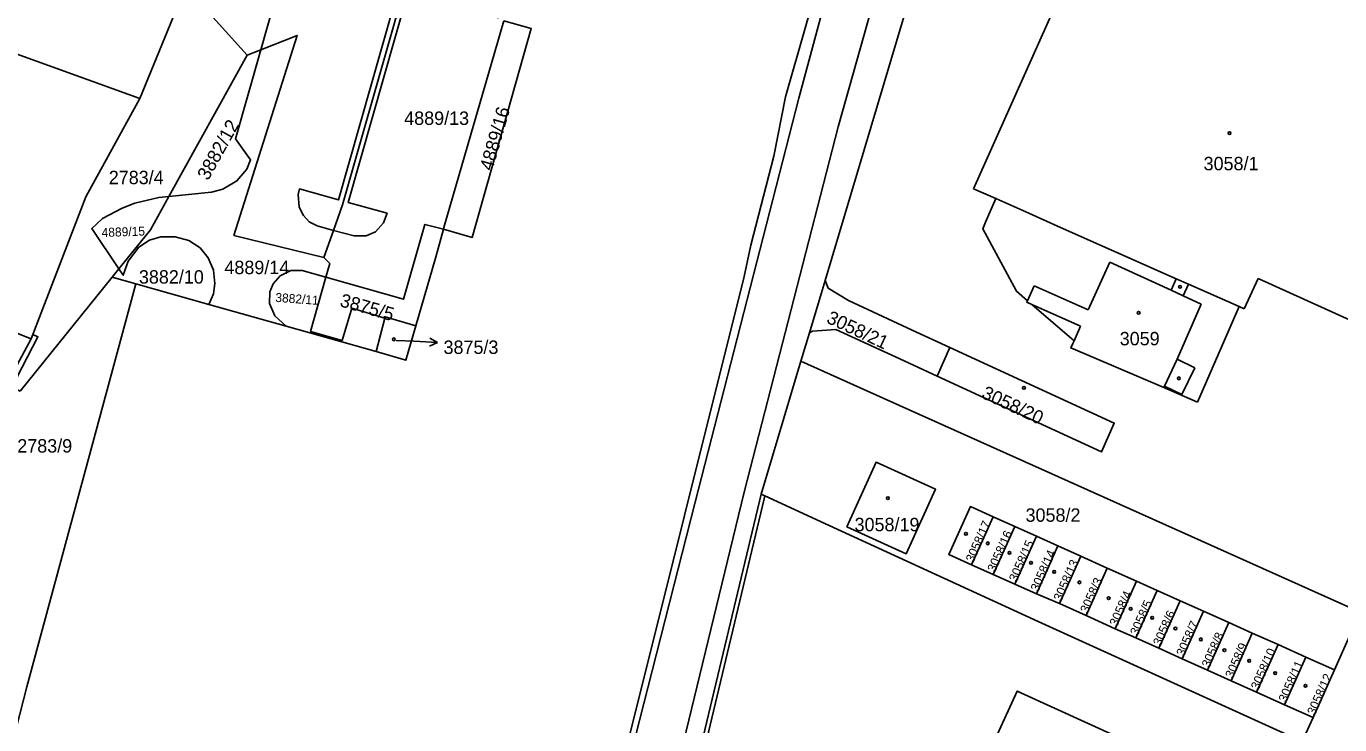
# Model space of a CAD drawing. Extents: x -527335 to -526256, y -1079142 to -1077809.
# Drawn here: x -526891.4 to -526725, y -1078894.6 to -1078806.1 of the extents above; entities that cross this region are included whole.
import ezdxf

# ---------------------------------------------------------------- set-up
doc = ezdxf.new("R2010")
doc.units = 0
for name, color, linetype in [('Vrstva 1', 7, 'Continuous'), ('Vrstva 2', 7, 'Continuous'), ('Vrstva 4', 7, 'Continuous'), ('Vrstva 5', 7, 'Continuous'), ('Vrstva 7', 7, 'Continuous')]:
    doc.layers.add(name, color=color, linetype=linetype)

msp = doc.modelspace()

# ---------------------------------------------------------------- linework, layer by layer
at = {"layer": 'Vrstva 1'}
for p, q in [((-526774.18, -1078784.68), (-526790.21, -1078838.32)), ((-526871.22, -1078801.11), (-526877.03, -1078815.27)), ((-526863.41, -1078809.75), (-526871.22, -1078801.11)), ((-526877.03, -1078815.27), (-526901.79, -1078806.32)), ((-526863.41, -1078809.75), (-526861.71, -1078809.08)), ((-526873.33, -1078827.67), (-526863.41, -1078809.75)), ((-526853.71, -1078835.4), (-526852.48, -1078831.96)), ((-526880.51, -1078837.89), (-526879.67, -1078836.85)), ((-526880.51, -1078837.89), (-526892.2, -1078852.35)), ((-526790.21, -1078838.32), (-526792.2, -1078844.96)), ((-526858.47, -1078844.1), (-526868.27, -1078841.34)), ((-526896.06, -1078843.62), (-526890.8, -1078845.7)), ((-526847.07, -1078847.31), (-526858.47, -1078844.1)), ((-526845.98, -1078843.08), (-526847.07, -1078847.31)), ((-526890.8, -1078845.7), (-526890.59, -1078845.16)), ((-526792.2, -1078844.96), (-526793.27, -1078848.55)), ((-526774.41, -1078846.79), (-526776, -1078850.44)), ((-526793.27, -1078848.55), (-526798.3, -1078865.38)), ((-526768.92, -1078868.26), (-526771.65, -1078874.34)), ((-526768.92, -1078868.26), (-526766.18, -1078869.49)), ((-526766.18, -1078869.49), (-526768.91, -1078875.57)), ((-526766.18, -1078869.49), (-526763.44, -1078870.72)), ((-526763.44, -1078870.72), (-526766.17, -1078876.8)), ((-526763.44, -1078870.72), (-526760.7, -1078871.95)), ((-526760.7, -1078871.95), (-526763.43, -1078878.03)), ((-526760.7, -1078871.95), (-526757.82, -1078873.24)), ((-526768.91, -1078875.57), (-526771.65, -1078874.34)), ((-526757.82, -1078873.24), (-526760.52, -1078879.26)), ((-526757.82, -1078873.24), (-526754.45, -1078874.76)), ((-526766.17, -1078876.8), (-526768.91, -1078875.57)), ((-526757.15, -1078880.77), (-526754.45, -1078874.76)), ((-526754.45, -1078874.76), (-526750.74, -1078876.42)), ((-526763.43, -1078878.03), (-526766.17, -1078876.8)), ((-526753.44, -1078882.44), (-526750.74, -1078876.42)), ((-526750.83, -1078883.61), (-526748.13, -1078877.59)), ((-526750.74, -1078876.42), (-526748.13, -1078877.59)), ((-526748.13, -1078877.59), (-526745.22, -1078878.9)), ((-526760.52, -1078879.26), (-526763.43, -1078878.03)), ((-526757.15, -1078880.77), (-526760.52, -1078879.26)), ((-526747.92, -1078884.92), (-526745.22, -1078878.9)), ((-526745.22, -1078878.9), (-526742.26, -1078880.23)), ((-526753.44, -1078882.44), (-526757.15, -1078880.77)), ((-526744.97, -1078886.25), (-526742.26, -1078880.23)), ((-526742.26, -1078880.23), (-526739.06, -1078881.66)), ((-526750.83, -1078883.61), (-526753.44, -1078882.44)), ((-526741.76, -1078887.69), (-526739.06, -1078881.66)), ((-526739.06, -1078881.66), (-526736.08, -1078883)), ((-526747.92, -1078884.92), (-526750.83, -1078883.61)), ((-526738.78, -1078889.03), (-526736.08, -1078883)), ((-526736.08, -1078883), (-526732.82, -1078884.46)), ((-526744.97, -1078886.25), (-526747.92, -1078884.92)), ((-526735.53, -1078890.49), (-526732.82, -1078884.46)), ((-526732.82, -1078884.46), (-526729.32, -1078886.04)), ((-526732.02, -1078892.07), (-526729.32, -1078886.04)), ((-526729.32, -1078886.04), (-526725.68, -1078887.67)), ((-526741.76, -1078887.69), (-526744.97, -1078886.25)), ((-526738.78, -1078889.03), (-526741.76, -1078887.69)), ((-526725.68, -1078887.67), (-526728.39, -1078893.7)), ((-526735.53, -1078890.49), (-526738.78, -1078889.03)), ((-526732.02, -1078892.07), (-526735.53, -1078890.49)), ((-526728.39, -1078893.7), (-526732.02, -1078892.07)), ((-526728.39, -1078893.7), (-526729.75, -1078896.73))]:
    msp.add_line(p, q, dxfattribs=at)
for points in [[(-526884.44, -1079141.53), (-526861.26, -1079084.28), (-526853.99, -1079074.79), (-526822.82, -1079003.24), (-526818.77, -1078991.73), (-526809.1, -1078957.32), (-526811.39, -1078950.51), (-526823.11, -1078928.49), (-526800.47, -1078837.81), (-526799.62, -1078833.84), (-526796.71, -1078822.54), (-526795.22, -1078815.04), (-526782.49, -1078770.61), (-526773.56, -1078736.49), (-526766.02, -1078728.13)], [(-526852.48, -1078831.96), (-526854.54, -1078831.4), (-526855.56, -1078830.87), (-526856.3, -1078830.07), (-526856.84, -1078829.04), (-526856.96, -1078827.42), (-526856.79, -1078826.7), (-526851.86, -1078828.1), (-526840.8, -1078789.17), (-526845.77, -1078787.84), (-526843.88, -1078781.19), (-526838.92, -1078782.52), (-526834.15, -1078765.67), (-526839.09, -1078764.32), (-526834.71, -1078748.94), (-526829.81, -1078750.39), (-526823.64, -1078728.74)], [(-526853.42, -1078763.04), (-526851.9, -1078763.85), (-526850.58, -1078764.43), (-526849.29, -1078765.38), (-526848.37, -1078766.67), (-526847.89, -1078768.42), (-526848.14, -1078770.69), (-526851.19, -1078772.01), (-526854.35, -1078783.07), (-526852.4, -1078785.74), (-526853.18, -1078788.48), (-526856.25, -1078789.82), (-526861.71, -1078809.08)], [(-526838.29, -1078782.98), (-526851.34, -1078828.74), (-526852.48, -1078831.96)], [(-526852.48, -1078831.96), (-526849.88, -1078832.66), (-526848.34, -1078832.64), (-526847.17, -1078832.15), (-526846.16, -1078831.02), (-526845.7, -1078829.8), (-526850.63, -1078828.45), (-526843.06, -1078801.82), (-526831.53, -1078805.04)], [(-526830.92, -1078805.41), (-526827.43, -1078806.4), (-526834.91, -1078832.86), (-526838.57, -1078831.82)], [(-526838.57, -1078831.82), (-526838.51, -1078831.59), (-526830.92, -1078805.41)], [(-526861.71, -1078809.08), (-526857.09, -1078807.27), (-526865.1, -1078832.61), (-526853.71, -1078835.4)], [(-526861.71, -1078809.08), (-526864.9, -1078820.36), (-526862.99, -1078823.04), (-526863.47, -1078824.2), (-526864.73, -1078825.69), (-526866.5, -1078826.75), (-526867.93, -1078827.11), (-526873.33, -1078827.67)], [(-526890.59, -1078845.16), (-526883.88, -1078827.7), (-526877.03, -1078815.27)], [(-526879.67, -1078836.85), (-526883.11, -1078831.73), (-526881.77, -1078830.48), (-526879.27, -1078829.14), (-526877.67, -1078828.53), (-526874.63, -1078827.81), (-526873.33, -1078827.67)], [(-526873.33, -1078827.67), (-526875.66, -1078831.89), (-526879.67, -1078836.85)], [(-526743.04, -1078853.75), (-526747.3, -1078851.87), (-526759.08, -1078846.86), (-526758.82, -1078846.29), (-526758.67, -1078845.95), (-526764.01, -1078841.37), (-526764.65, -1078841.08), (-526764.56, -1078840.89), (-526765.97, -1078839.68), (-526770.24, -1078831.76), (-526769.88, -1078830.92), (-526768.59, -1078827.94), (-526764.41, -1078829.8), (-526760.75, -1078831.42), (-526745.71, -1078838.09), (-526744.16, -1078838.78), (-526737.76, -1078841.62), (-526743.04, -1078853.75)], [(-526868.27, -1078841.34), (-526867.71, -1078840.01), (-526867.51, -1078838.71), (-526867.69, -1078837.02), (-526868.37, -1078835.46), (-526869.4, -1078834.19), (-526870.82, -1078833.24), (-526872.55, -1078832.77), (-526874.35, -1078832.78), (-526875.82, -1078833.22), (-526877.17, -1078834.08), (-526878.52, -1078835.85), (-526879.13, -1078837.66), (-526879.67, -1078836.85)], [(-526853.45, -1078837.91), (-526843.6, -1078840.7), (-526840.9, -1078831.21), (-526838.57, -1078831.82)], [(-526838.57, -1078831.82), (-526839.55, -1078835.47), (-526842.04, -1078844.04)], [(-526853.71, -1078835.4), (-526852.96, -1078836.18), (-526853.45, -1078837.91)], [(-526858.47, -1078844.1), (-526859.93, -1078842.78), (-526860.61, -1078841.23), (-526860.55, -1078839.74), (-526860.13, -1078838.75), (-526859.23, -1078837.72), (-526857.88, -1078837.05), (-526856.47, -1078837.05), (-526853.45, -1078837.91)], [(-526868.27, -1078841.34), (-526877.52, -1078838.73), (-526880.51, -1078837.89)], [(-526853.45, -1078837.91), (-526855.39, -1078844.76), (-526851.4, -1078845.9), (-526850.15, -1078841.82), (-526845.98, -1078843.08)], [(-526790.21, -1078838.32), (-526789.81, -1078839.3), (-526787.25, -1078840.87), (-526779.18, -1078844.59), (-526774.41, -1078846.79)], [(-526842.04, -1078844.04), (-526843.31, -1078848.43), (-526847.07, -1078847.31)], [(-526842.04, -1078844.04), (-526845.93, -1078842.9), (-526845.98, -1078843.08)], [(-526898.78, -1078860.48), (-526897.08, -1078857.34), (-526890.8, -1078845.7)], [(-526892.2, -1078852.35), (-526893.23, -1078851.84), (-526889.93, -1078845.45), (-526890.59, -1078845.16)], [(-526776, -1078850.44), (-526780.74, -1078848.26), (-526788.84, -1078844.53), (-526791.8, -1078844.72), (-526792.2, -1078844.96)], [(-526774.41, -1078846.79), (-526753.58, -1078856.38), (-526755.17, -1078860.03), (-526776, -1078850.44)], [(-526793.27, -1078848.55), (-526782.84, -1078853.23), (-526722.4, -1078880.36), (-526725.68, -1078887.67)], [(-526787.47, -1078869.51), (-526783.74, -1078861.33), (-526776.2, -1078864.77), (-526779.93, -1078872.94), (-526787.47, -1078869.51)], [(-526798.3, -1078865.38), (-526811.61, -1078921.08), (-526810.31, -1078930.61), (-526807.74, -1078936.51), (-526806.27, -1078939.34), (-526804.43, -1078942.06), (-526791.96, -1078947.57)], [(-526798.3, -1078865.38), (-526797.84, -1078865.59), (-526789.67, -1078869.35), (-526763.21, -1078881.51), (-526729.75, -1078896.73)], [(-526771.65, -1078874.34), (-526774.53, -1078873.05), (-526771.8, -1078866.97), (-526768.92, -1078868.26)], [(-526771.85, -1078903.46), (-526765.87, -1078890.34), (-526739.82, -1078902.21)]]:
    msp.add_lwpolyline(points, dxfattribs=at)
at = {"layer": 'Vrstva 4'}
for p, q in [((-526784.46, -1078781.51), (-526793.55, -1078815.2)), ((-526778.89, -1078784.53), (-526788.56, -1078818.84)), ((-526771.41, -1078826.69), (-526760.66, -1078802.66)), ((-526793.55, -1078815.2), (-526806.66, -1078866.4)), ((-526788.56, -1078818.84), (-526800.46, -1078865.14)), ((-526768.59, -1078827.94), (-526771.41, -1078826.69)), ((-526756.89, -1078842.04), (-526754.14, -1078835.98)), ((-526754.14, -1078835.98), (-526746.37, -1078839.55)), ((-526877.52, -1078838.73), (-526891.36, -1078889.81)), ((-526764.56, -1078840.89), (-526763.7, -1078839)), ((-526763.7, -1078839), (-526756.89, -1078842.04)), ((-526746.37, -1078839.55), (-526745.71, -1078838.09)), ((-526744.16, -1078838.78), (-526744.83, -1078840.26)), ((-526737.13, -1078841.9), (-526735.32, -1078838.08)), ((-526735.32, -1078838.08), (-526723.31, -1078843.53)), ((-526744.83, -1078840.26), (-526746.37, -1078839.55)), ((-526744.83, -1078840.26), (-526742.56, -1078841.3)), ((-526757.83, -1078844.12), (-526764.01, -1078841.37)), ((-526742.56, -1078841.3), (-526745.59, -1078848.3)), ((-526737.76, -1078841.62), (-526737.13, -1078841.9)), ((-526758.67, -1078845.95), (-526757.83, -1078844.12)), ((-526747.22, -1078851.7), (-526745.59, -1078848.3)), ((-526745.59, -1078848.3), (-526743.36, -1078849.37)), ((-526743.36, -1078849.37), (-526745, -1078852.77)), ((-526747.22, -1078851.7), (-526747.3, -1078851.87)), ((-526745, -1078852.77), (-526747.22, -1078851.7)), ((-526800.46, -1078865.14), (-526812.19, -1078913.33)), ((-526811.13, -1078921.2), (-526797.93, -1078865.98)), ((-526797.93, -1078865.98), (-526797.84, -1078865.59)), ((-526806.66, -1078866.4), (-526818.03, -1078910.91)), ((-526891.36, -1078889.81), (-526913.97, -1078978.24))]:
    msp.add_line(p, q, dxfattribs=at)
at = {"layer": 'Vrstva 5'}
for centre in [(-526738.96, -1078819.64), (-526745.24, -1078839.13), (-526750.48, -1078842.41), (-526844.83, -1078845.77), (-526745.38, -1078850.71), (-526765.01, -1078851.93), (-526782.25, -1078865.9), (-526772.36, -1078870.42), (-526769.6, -1078871.62), (-526766.85, -1078872.81), (-526764.12, -1078874.08), (-526761.18, -1078875.24), (-526757.99, -1078876.56), (-526754.28, -1078878.57), (-526751.49, -1078879.91), (-526748.76, -1078881.05), (-526745.83, -1078882.41), (-526742.59, -1078883.79), (-526739.62, -1078885.16), (-526736.47, -1078886.5), (-526733.18, -1078888.06), (-526729.35, -1078889.67)]:
    msp.add_circle(centre, 0.175, dxfattribs=at)
at = {"layer": 'Vrstva 7'}
for p, q in [((-526844.55, -1078845.91), (-526842.3, -1078846.02)), ((-526842.3, -1078846.02), (-526839.3, -1078846.18)), ((-526839.3, -1078846.18), (-526840.28, -1078845.62)), ((-526839.3, -1078846.18), (-526840.33, -1078846.62))]:
    msp.add_line(p, q, dxfattribs=at)

# ---------------------------------------------------------------- texts
at = {"layer": 'Vrstva 2'}
for s, p in [('4889/13', (-526843.53, -1078818.6)), ('3058/1', (-526742.25, -1078824.35)), ('2783/4', (-526880.96, -1078826.11)), ('4889/14', (-526866.31, -1078837.51)), ('3882/10', (-526877.14, -1078838.71)), ('3875/3', (-526838.55, -1078847.62)), ('3059', (-526752.88, -1078846.53)), ('2783/9', (-526892.55, -1078860.12)), ('3058/2', (-526764.81, -1078868.89)), ('3058/19', (-526786.47, -1078870.09))]:
    msp.add_text(s, height=1.7, dxfattribs=at).set_placement(p)
for s, height, rotation, p in [('4889/16', 1.7, 74, (-526832.37, -1078824.5)), ('3882/12', 1.7, 61, (-526868.37, -1078825.74)), ('4889/15', 1.139, 2, (-526881.85, -1078832.81)), ('3882/11', 1.139, 356, (-526859.89, -1078841.02)), ('3875/5', 1.7, 344, (-526851.79, -1078841.56)), ('3058/21', 1.7, 335, (-526790.15, -1078843.61)), ('3058/20', 1.7, 335, (-526770.5, -1078853.14)), ('3058/17', 1.14, 66, (-526771.41, -1078874.13)), ('3058/16', 1.14, 66, (-526768.67, -1078875.36)), ('3058/15', 1.14, 66, (-526765.93, -1078876.59)), ('3058/14', 1.14, 66, (-526763.19, -1078877.82)), ('3058/13', 1.14, 66, (-526760.28, -1078879.05)), ('3058/3', 1.14, 66, (-526756.91, -1078880.56)), ('3058/4', 1.14, 66, (-526753.2, -1078882.23)), ('3058/5', 1.14, 66, (-526750.59, -1078883.4)), ('3058/6', 1.14, 66, (-526747.68, -1078884.71)), ('3058/7', 1.14, 66, (-526744.73, -1078886.04)), ('3058/8', 1.14, 66, (-526741.52, -1078887.48)), ('3058/9', 1.14, 66, (-526738.54, -1078888.82)), ('3058/10', 1.14, 66, (-526735.29, -1078890.28)), ('3058/11', 1.14, 66, (-526731.78, -1078891.86)), ('3058/12', 1.14, 66, (-526728.15, -1078893.49))]:
    msp.add_text(s, height=height, rotation=rotation, dxfattribs=at).set_placement(p)

doc.saveas('drawing.dxf')
